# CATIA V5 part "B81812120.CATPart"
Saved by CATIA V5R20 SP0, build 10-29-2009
Part number: B81812120
Revision: 6
Definition: design
Nomenclature: B81812120
Source: made
Description: NOT SPECIFIED
Bounding box of the stored display mesh (mm): x -8 to 8, y -8 to 8, z 0 to 120
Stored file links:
  C:\Users\Raffaele\Desktop\3D X SITO CF\BOLEX\6-PILLAR REF 818\B81812120.CATPart
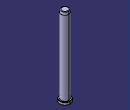
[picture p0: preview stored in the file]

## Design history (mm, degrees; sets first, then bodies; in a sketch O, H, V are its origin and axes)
Body1 "MANIFOLD_SOLID_BREP #370" (main body)
  Solid1: solid without history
